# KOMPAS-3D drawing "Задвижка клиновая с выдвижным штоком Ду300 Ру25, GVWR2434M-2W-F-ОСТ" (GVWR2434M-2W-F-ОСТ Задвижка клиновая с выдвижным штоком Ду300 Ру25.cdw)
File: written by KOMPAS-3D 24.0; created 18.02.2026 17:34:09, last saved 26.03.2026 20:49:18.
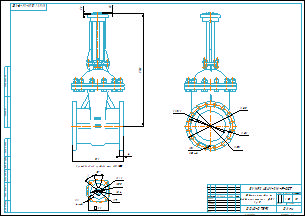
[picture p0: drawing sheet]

Document properties: Автор: R2D2; Форматы листов документа: A2; Полное имя файла: GVWR2434M-2W-F-ОСТ Задвижка клиновая с выдвижным штоком Ду300 Ру25.m3d; Масса: 265; Наименование: Задвижка клиновая с выдвижным штоком Ду300 Ру25; Количество листов документа: 1; Примечание: D040-07592

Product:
- Part/product: Задвижка клиновая с выдвижным штоком Ду300 Ру25  | designation GVWR2434M-2W-F-ОСТ
    Масса: 265
    Раздел спецификации: Прочие изделия
    Примечание: D040-07592

Views: Проекционный вид 3
Referenced files in E:\Работа\Зайцев\Для компаса\: чертеж DN.ru А3.cdt
Referenced files in E:\Работа\Зайцев\GVWR2434M-2W-F-ОСТ Задвижка клиновая с выдвижным штоком DN.ru Ду50-300 Ру25\исходные материалы\DN300\DN300\: GVWR2434M-2W-F-ОСТ Задвижка клиновая с выдвижным штоком Ду300 Ру25.m3d
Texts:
  Присоединение привода тип АК (В)
  чертеж DN.ru А3.cdt
  Задвижка клиновая с
  выдвижным штоком Ду300
  Ру25
  GVWR2434M-2W-F-ОСТ
  Задвижка клиновая с выдвижным штоком Ду300 Ру25
  GVWR2434M-2W-F-ОСТ Задвижка клиновая с выдвижным штоком Ду300 Ру25
Dimensions and other numbers on the sheet: 200; 220; 155; 84; 70; 22; 4 отв.; 1:5; 0; 1; 2; 265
